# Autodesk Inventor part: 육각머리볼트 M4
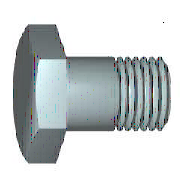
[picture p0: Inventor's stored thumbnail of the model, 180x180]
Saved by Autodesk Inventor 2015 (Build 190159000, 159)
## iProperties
IsCustomPart: 1
Created: 2012-02
Part Number: 육각머리볼트 M4
Material: 스테인리스강
Description: 6각 머리 볼트 및 6각 머리 나사
Document SubType Name: Modeling
Standard: KS B 1002
Designer: mduedu
Standards Organization: KS
Language: ko-KR
Size Designation: A + B M4 x 10
Categories: <MemberInstance><Categories><Category DisplayName="조임쇠" InternalName="e4da775c-781d-43d5-af7c-5136215cf5a6" Mnemonic="FSTN"><Category DisplayName="볼트" InternalN
Density: 8.08 g/cm^3
Mass: 1.91435 g
Surface Area: 2.70732 cm^2
Volume: 0.236925 cm^3
Appearance: 반광택
Author: mduedu
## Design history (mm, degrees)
sketch "스케치1"
  geometry: L1 (0, 2.94)-(0, 2); L2 (2.1, 2)-(10, 2); L3 (10, 2)-(10, 0); L4 (10, 0)-(-0.4, 0); L5 (-2.48, 0)-(12.08, 0) reference; L6 (-0.4, 0)-(-0.4, 2.94); L7 (-0.4, 2.94)-(0, 2.94); L8 (2.1, 2)-(1.67, 2); L9 (1.67, 2)-(0, 2); L10 (0, -0.588)-(0, 3.528) reference
  constraints: 16 end point, 2 collinear, 2 perpendicular, 1 parallel
  dimensions: "d0" = 10 distance between parallel lines of L3 L1 (= NLG); "d1" = 7.9 distance from line of L2.start L3 (= GEL); "d2" = 4 diameter of L2 L4 (= GD); "d9" = 0.4001 distance between parallel lines of L6 L1 (computed from SD); "d10" = 5.88 diameter of L7 L4 (= SD2); "d13" = 0.42952 distance of L2.start L8.end (computed from GAL); "d14" = 4 diameter of L9 L4 (= BDM)
revolve "본체" sketch "스케치1" stored, may be unused: angle "d12" = 90 deg
sketch "스케치2"
  geometry: L1 (0, 4.041)-(3.5, 2.021); L2 (3.5, 2.021)-(3.5, -2.021); L3 (3.5, -2.021)-(0, -4.041); L4 (0, -4.041)-(-3.5, -2.021); L5 (-3.5, -2.021)-(-3.5, 2.021); L6 (-3.5, 2.021)-(0, 4.041); 2 further points
  constraints: 12 end point, 1 coincident, 1 vertical, 11 other
  dimensions: "d11" = 7 distance between parallel lines of L5 L2 (= SW)
extrude "머리" join sketch "스케치2" distance "d3" = 2.4 (= KOH - SD); taper "d4" = 0 deg
sketch "스케치4"
  geometry: L1 (-2.8, 3.5)-(-2.8, 4.041); L2 (-2.8, 4.041)-(-2.487, 4.041); L3 (-2.487, 4.041)-(-2.8, 3.5); L4 (-3.28, 0)-(0.08, 0) reference; L5 (-0.4, 4.041)-(-2.8, 4.041) reference; L6 (-2.8, 2.021)-(-2.8, 4.041) reference
  constraints: 6 end point, 2 collinear, 1 perpendicular, 1 vertical
  dimensions: "d5" = 30 deg angle of L3 L1 (= ANG1); "d19" = 7 diameter of L1.start L4 (= SW0)
revolve "모따기1" sketch "스케치4" stored, may be unused: angle "d21" = 90 deg
workplane "Work Plane1"
body "Solid1"
feature "스레드" dims "d15" = 7.9 (= GEL), "d16" = 0
chamfer "모따기2" distance "d6" = 0.42941 (= -0.5 x SPD + 0.5 x GD); stored, may be unused: second distance "d7" = 0.42952 (computed from GUL), angle "d55" = 45 deg
other parameters: "NLG" = 10 [user parameter; used in 1 equation term], "GD" = 4 (= NND) [user parameter; used in 2 equation terms], "BDM" = 4 (= NND) [user parameter; used in 1 equation term], "KOH" = 2.8 [user parameter; used in 1 equation term], "GEL" = 7.9 [user parameter; used in 2 equation terms], "SW" = 7 [user parameter; used in 3 equation terms], "SW0" = 7 (= SW) [user parameter; used in 1 equation term], "SPD" = 3.14117 (= NND - 1.2269 x PTC) [user parameter; used in 1 equation term], "SD2" = 5.88 (= SDH) [user parameter; used in 1 equation term], "SD" = 0.4 [user parameter; used in 2 equation terms], "ANG1" = 30 deg [user parameter; used in 1 equation term], "GAL" = 0.42941 (= 0.61345 x PTC) [user parameter; used in 1 equation term], "GUL" = 0.42941 (= 0.61345 x PTC) [user parameter; used in 1 equation term], "d8" = 0, "RR" = 0.2 [user parameter], "d57" = 0, "d58" = 0, "TPU" = 14.28571 (computed from PTC) [user parameter], "GD1" = 3.14117 (= THREADDIA - 1.2269 x PTC) [user parameter], "THREADDIA" = 4 [user parameter; used in 1 equation term], "SDH" = 5.88 [user parameter; used in 1 equation term], "SDHG" = 2.1 [user parameter], "TOA" = 30 deg [user parameter], "PTC" = 0.7 [user parameter; used in 5 equation terms], "NND" = 4 [user parameter; used in 3 equation terms], "E0" = 8.085 (= 1.155 x SW) [user parameter]
